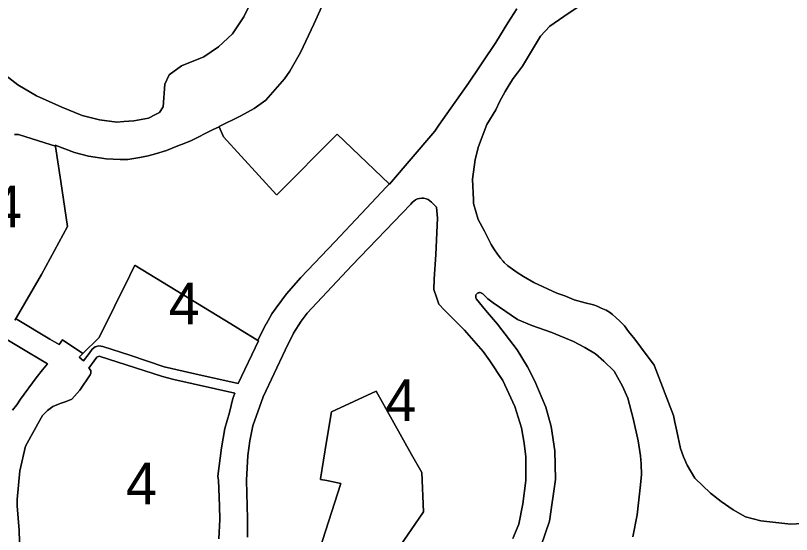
# Model space of a CAD drawing. Extents: x 598968 to 613553, y 4409678 to 4430833.
# Drawn here: x 610893 to 611116.4, y 4416459.8 to 4416609.3 of the extents above; entities that cross this region are included whole.
import ezdxf

# ---------------------------------------------------------------- set-up
doc = ezdxf.new("R2010")
doc.units = 0
doc.layers.add('1', color=7, linetype='Continuous')
doc.layers.add('ZONA 4. CASES UNIFAMILIRAS AÏLLADES EN PARCEL.LES', color=7, linetype='Continuous')

msp = doc.modelspace()

# ---------------------------------------------------------------- linework, layer by layer
at = {"layer": '1'}
for points in [[(610961.184, 4416613.8732), (610958.7248, 4416608.878), (610955.4757, 4416603.9853), (610951.4952, 4416600.27), (610947.1994, 4416597.4186), (610940.8094, 4416594.766), (610937.27, 4416592.1919), (610936.0337, 4416589.5134), (610935.5234, 4416582.9955), (610934.4335, 4416581.3607), (610933.2877, 4416580.7629), (610931.3004, 4416579.7259), (610927.04, 4416578.9784), (610924.182, 4416578.755), (610922.1426, 4416578.5957), (610917.2304, 4416579.2049), (610912.1833, 4416580.5148), (610906.335, 4416582.909), (610899.0802, 4416586.1025), (610893.7131, 4416589.3305), (610887.1816, 4416594.3181)], [(610887.1816, 4416594.3181), (610893.7131, 4416589.3305), (610899.0802, 4416586.1025), (610906.335, 4416582.909), (610912.1833, 4416580.5148), (610917.2304, 4416579.2049), (610922.1426, 4416578.5957), (610924.182, 4416578.755), (610927.04, 4416578.9784), (610931.3004, 4416579.7259), (610933.2877, 4416580.7629), (610934.4335, 4416581.3607), (610935.5234, 4416582.9955), (610936.0337, 4416589.5134), (610937.27, 4416592.1919), (610940.8094, 4416594.766), (610947.1994, 4416597.4186), (610951.4952, 4416600.27), (610955.4757, 4416603.9853), (610958.7248, 4416608.878), (610961.184, 4416613.8732)], [(610892.7107, 4416575.0409), (610893.9086, 4416575.0409), (610901.4437, 4416572.577), (610904.4817, 4416571.5979), (610904.4763, 4416571.6327), (610904.4349, 4416571.9025), (610904.4403, 4416571.9005), (610909.9969, 4416569.8168), (610914.0019, 4416568.7894), (610919.1245, 4416568.0325), (610923.1262, 4416567.8479), (610925.3954, 4416567.7714), (610928.8165, 4416568.3364), (610931.1583, 4416568.8195), (610933.3142, 4416569.4638), (610936.4387, 4416570.3976), (610939.7356, 4416571.7509), (610941.5996, 4416572.45), (610943.7244, 4416573.2468), (610949.7511, 4416576.316), (610951.6354, 4416577.2366), (610951.6236, 4416577.2639), (610951.6172, 4416577.2787), (610951.629, 4416577.2845), (610951.6172, 4416577.3118), (610957.8684, 4416580.3459), (610961.7173, 4416582.5227), (610965.0822, 4416584.9171), (610970.4878, 4416591.0592), (610972.0152, 4416593.2056), (610975.0943, 4416598.6592), (610978.9476, 4416606.7691), (610981.2076, 4416611.8791)], [(611037.339, 4416611.1665), (611034.741, 4416607.1495), (611031.2771, 4416601.5256), (611027.408, 4416595.6004), (611026.6333, 4416594.5253), (611023.4683, 4416589.764), (611014.8872, 4416577.6602), (611013.7072, 4416575.9901), (611000.7274, 4416560.7202), (611000.6511, 4416560.7926), (611000.6347, 4416560.7752), (611000.6511, 4416560.7596), (610999.8384, 4416559.8954), (610992.5548, 4416552.1508), (610984.962, 4416544.0775), (610975.1184, 4416533.8126), (610971.056, 4416529.1494), (610968.0389, 4416525.113), (610966.7828, 4416523.3187), (610965.1493, 4416520.4247), (610965.0964, 4416520.3309), (610962.7983, 4416515.6993), (610962.7932, 4416515.6891), (610962.7847, 4416515.6749), (610962.9704, 4416515.5563), (610957.1035, 4416503.2946), (610944.6427, 4416506.0886), (610935.8082, 4416508.1204), (610925.9499, 4416511.493), (610918.193, 4416513.9774), (610917.0455, 4416514.1503), (610915.9768, 4416513.8361), (610915.0964, 4416513.145), (610914.1689, 4416511.8887), (610912.6098, 4416509.8266), (610911.2976, 4416510.8447), (610912.4052, 4416511.9294), (610912.3853, 4416511.943), (610906.5731, 4416515.9097), (610905.5541, 4416514.4821), (610902.9127, 4416516.0703), (610893.4876, 4416521.7378), (610893.0763, 4416521.9612), (610892.7939, 4416521.5109)], [(611122.8662, 4416463.1736), (611116.2063, 4416462.7335), (611107.5764, 4416463.7133), (611103.2363, 4416464.8532), (611099.6665, 4416466.8631), (611096.1764, 4416469.323), (611093.1364, 4416471.673), (611088.5965, 4416476.0128), (611086.3665, 4416479.7727), (611085.3565, 4416482.1327), (611084.5165, 4416484.5926), (611083.4265, 4416489.6025), (611082.8365, 4416492.1125), (611082.4365, 4416494.1125), (611076.9266, 4416508.6123), (611072.9966, 4416513.8121), (611071.3266, 4416516.0721), (611069.5066, 4416518.302), (611068.3867, 4416519.8819), (611066.9167, 4416521.3219), (611064.9167, 4416523.1818), (611064.0267, 4416523.8118), (611063.0367, 4416524.3918), (611061.6767, 4416524.9818), (611060.4567, 4416525.5617), (611059.4168, 4416525.9117), (611057.0168, 4416526.5317), (611053.8768, 4416527.3616), (611051.1869, 4416528.5015), (611048.8869, 4416529.2614), (611042.2471, 4416532.4213), (611039.257, 4416534.1212), (611037.457, 4416535.2912), (611034.727, 4416537.1711), (611033.7371, 4416538.1811), (611033.3871, 4416538.5711), (611032.6471, 4416539.401), (611031.7371, 4416540.541), (611030.6972, 4416542.061), (611029.9871, 4416543.3609), (611028.0871, 4416547.1708), (611026.2271, 4416550.5308), (611024.8871, 4416555.1607), (611024.8271, 4416556.1607), (611024.6081, 4416562.1249), (611024.6071, 4416562.1506), (611025.3271, 4416567.7605), (611026.2671, 4416571.5305), (611028.727, 4416577.8904), (611031.347, 4416582.1404), (611032.357, 4416584.4504), (611033.977, 4416587.4004), (611035.1169, 4416589.3004), (611036.337, 4416591.1104), (611037.547, 4416592.7403), (611039.0169, 4416594.7204), (611044.2068, 4416603.3303), (611046.8467, 4416606.2304), (611050.9267, 4416608.9704), (611056.1466, 4416612.5804)], [(610959.7955, 4416459.0372), (610959.7955, 4416464.3324), (610959.7955, 4416464.3654), (610959.5093, 4416475.3822), (610959.5087, 4416475.4054), (610959.9412, 4416482.5337), (610960.519, 4416486.8192), (610961.3838, 4416491.1394), (610964.3386, 4416499.4918), (610970.6194, 4416512.8521), (610973.0698, 4416517.8203), (610975.2318, 4416521.2765), (610976.9615, 4416523.5807), (610989.8163, 4416537.2328), (611006.8247, 4416554.9458), (611007.2137, 4416555.4328), (611007.6754, 4416555.8514), (611008.1978, 4416556.1912), (611008.7678, 4416556.4434), (611009.3708, 4416556.6012), (611009.9912, 4416556.661), (611010.6132, 4416556.6211), (611011.2209, 4416556.4824), (611011.7986, 4416556.2486), (611012.3317, 4416555.9257), (611012.8065, 4416555.5219), (611014.2479, 4416554.0819), (611014.4642, 4416550.9138), (611014.4632, 4416550.8932), (611014.0325, 4416540.4424), (611013.5281, 4416533.3861), (611013.4564, 4416530.361), (611014.3208, 4416527.9139), (611014.8974, 4416526.1859), (611016.555, 4416524.3857), (611022.2594, 4416518.6572), (611027.6647, 4416512.5371), (611029.5386, 4416509.801), (611033.2861, 4416504.1128), (611036.7471, 4416496.671), (611038.6929, 4416490.5507), (611039.4857, 4416486.0865), (611039.9148, 4416482.1582), (611039.9148, 4416482.1251), (611039.9148, 4416475.3179), (611039.05, 4416468.6216), (611037.897, 4416462.7894), (611036.1672, 4416458.6131)], [(611044.3612, 4416456.5831), (611046.7583, 4416463.6503), (611048.4521, 4416475.6487), (611048.4528, 4416475.6534), (611048.2566, 4416483.8879), (611047.1955, 4416490.9158), (611045.6628, 4416496.4519), (611042.5142, 4416503.9842), (611040.4706, 4416508.0675), (611037.4054, 4416512.9751), (611031.78, 4416520.4171), (611028.3218, 4416524.4219), (611025.7674, 4416527.5627), (611025.655, 4416527.7282), (611025.5722, 4416527.9102), (611025.5218, 4416528.1038), (611025.5064, 4416528.2863), (611025.505, 4416528.3031), (611025.5224, 4416528.5022), (611025.5735, 4416528.6957), (611025.6567, 4416528.8774), (611025.7698, 4416529.0425), (611025.9092, 4416529.1858), (611026.0711, 4416529.3033), (611026.2505, 4416529.3915), (611026.4423, 4416529.448), (611026.641, 4416529.4709), (611026.8407, 4416529.4595), (611027.0355, 4416529.4144), (611027.2198, 4416529.3368), (611027.3882, 4416529.2291), (611027.5358, 4416529.0941), (611028.9721, 4416527.7089), (611030.5618, 4416526.5029), (611037.5176, 4416521.7522), (611041.644, 4416519.9855), (611047.4602, 4416517.9832), (611053.6858, 4416515.3796), (611056.9083, 4416513.6128), (611060.013, 4416511.8461), (611062.4101, 4416509.7652), (611065.3576, 4416506.8598), (611067.8004, 4416502.5221), (611069.3331, 4416499.0279), (611070.8266, 4416493.2563), (611072.2438, 4416486.7508), (611072.9512, 4416482.4319), (611073.1084, 4416480.1153), (611073.2263, 4416476.9744), (611073.2254, 4416476.9657), (611072.832, 4416473.2193), (611071.9675, 4416465.4454), (611070.7074, 4416459.0989)], [(610877.1079, 4416523.9232), (610902.1819, 4416508.9566), (610900.8029, 4416507.2609), (610898.94, 4416504.9343), (610894.477, 4416498.8147), (610893.3432, 4416497.1282), (610892.149, 4416495.6191)], [(610894.422, 4416448.185), (610894.0668, 4416460.9603), (610893.5086, 4416468.0579), (610893.4603, 4416469.924), (610894.2233, 4416478.1052), (610895.8472, 4416485.2534), (610900.3702, 4416493.3963), (610900.7761, 4416494.0553), (610902.2477, 4416495.5256), (610903.77, 4416496.641), (610905.9012, 4416497.5535), (610907.6265, 4416498.1112), (610909.2504, 4416498.8211), (610911.5336, 4416501.4066), (610914.472, 4416505.813), (610914.6625, 4416506.2569), (610914.6625, 4416506.29), (610914.6625, 4416506.6057), (610914.6625, 4416506.6388), (610914.6625, 4416506.9547), (610914.6625, 4416506.9877), (610914.135, 4416507.6695), (610916.4084, 4416510.8555), (610917.1385, 4416511.1727), (610935.3405, 4416505.2614), (610938.6179, 4416504.4396), (610956.1265, 4416500.4673), (610955.5781, 4416498.9302), (610954.6388, 4416494.9277), (610953.2687, 4416490.3143), (610952.3554, 4416484.7377), (610951.2882, 4416476.5592), (610951.2907, 4416476.5454), (610951.4912, 4416475.4439), (610951.7422, 4416468.014), (610951.8437, 4416464.1612), (610951.8432, 4416464.149), (610951.59, 4416458.5338)], [(610996.0807, 4416445.3826), (611006.9316, 4416461.1561), (611010.4947, 4416466.3358), (611009.976, 4416477.6224), (611007.0546, 4416482.8218), (610996.8137, 4416501.048), (610984.0145, 4416495.0933), (610982.5855, 4416486.5816), (610980.8698, 4416475.8276), (610980.8422, 4416475.6548), (610982.6031, 4416475.3266), (610986.6796, 4416474.4915), (610980.5379, 4416455.3781)]]:
    msp.add_lwpolyline(points, dxfattribs=at)
msp.add_lwpolyline([(611000.6347, 4416560.7752), (610985.5741, 4416575.0839), (610968.2574, 4416557.6073), (610968.1895, 4416557.6888), (610968.1179, 4416557.6165), (610952.8749, 4416574.3663), (610951.6354, 4416577.2366), (610949.7511, 4416576.316), (610943.7244, 4416573.2468), (610941.5996, 4416572.45), (610939.7356, 4416571.7509), (610936.4387, 4416570.3976), (610933.3142, 4416569.4638), (610931.1583, 4416568.8195), (610928.8165, 4416568.3364), (610925.3954, 4416567.7714), (610923.1262, 4416567.8479), (610919.1245, 4416568.0325), (610914.0019, 4416568.7894), (610909.9969, 4416569.8168), (610904.4403, 4416571.9005), (610904.4349, 4416571.9025), (610904.4763, 4416571.6327), (610904.4817, 4416571.5979), (610904.5125, 4416571.588), (610906.0394, 4416561.4712), (610907.9887, 4416548.5557), (610900.522, 4416534.665), (610893.2803, 4416522.3092), (610893.0972, 4416521.9969), (610893.0763, 4416521.9612), (610893.4876, 4416521.7378), (610902.9127, 4416516.0703), (610905.5541, 4416514.4821), (610906.5731, 4416515.9097), (610912.3853, 4416511.943), (610912.4052, 4416511.9294), (610917.0686, 4416516.4962), (610925.9387, 4416534.4256), (610927.3885, 4416537.3561), (610927.4991, 4416537.2885), (610954.9812, 4416520.4866), (610959.0741, 4416517.9844), (610961.278, 4416516.637), (610961.991, 4416516.1817), (610962.7847, 4416515.6749), (610962.7932, 4416515.6891), (610962.7983, 4416515.6993), (610965.0964, 4416520.3309), (610965.1493, 4416520.4247), (610966.7828, 4416523.3187), (610968.0389, 4416525.113), (610971.056, 4416529.1494), (610975.1184, 4416533.8126), (610984.962, 4416544.0775), (610992.5548, 4416552.1508), (610999.8384, 4416559.8954), (611000.6511, 4416560.7596)], close=True, dxfattribs=at)
at = {"layer": 'ZONA 4. CASES UNIFAMILIRAS AÏLLADES EN PARCEL.LES'}
for points in [[(610981.2076, 4416611.8791), (610978.9476, 4416606.7691), (610975.0943, 4416598.6592), (610972.0152, 4416593.2056), (610970.4878, 4416591.0592), (610965.0822, 4416584.9171), (610961.7173, 4416582.5227), (610957.8684, 4416580.3459), (610951.6172, 4416577.3118), (610951.629, 4416577.2845), (610951.6172, 4416577.2787), (610951.6236, 4416577.2639), (610951.6354, 4416577.2366), (610952.8749, 4416574.3663), (610968.1179, 4416557.6165), (610968.1895, 4416557.6888), (610968.2574, 4416557.6073), (610985.5741, 4416575.0839), (611000.6347, 4416560.7752), (611000.6511, 4416560.7926), (611000.7274, 4416560.7202), (611013.7072, 4416575.9901), (611014.8872, 4416577.6602), (611023.4683, 4416589.764), (611026.6333, 4416594.5253), (611027.408, 4416595.6004), (611031.2771, 4416601.5256), (611034.741, 4416607.1495), (611037.339, 4416611.1665)], [(611056.1466, 4416612.5804), (611050.9267, 4416608.9704), (611046.8467, 4416606.2304), (611044.2068, 4416603.3303), (611039.0169, 4416594.7204), (611037.547, 4416592.7403), (611036.337, 4416591.1104), (611035.1169, 4416589.3004), (611033.977, 4416587.4004), (611032.357, 4416584.4504), (611031.347, 4416582.1404), (611028.727, 4416577.8904), (611026.2671, 4416571.5305), (611025.3271, 4416567.7605), (611024.6071, 4416562.1506), (611024.6081, 4416562.1249), (611024.8271, 4416556.1607), (611024.8871, 4416555.1607), (611026.2271, 4416550.5308), (611028.0871, 4416547.1708), (611029.9871, 4416543.3609), (611030.6972, 4416542.061), (611031.7371, 4416540.541), (611032.6471, 4416539.401), (611033.3871, 4416538.5711), (611033.7371, 4416538.1811), (611034.727, 4416537.1711), (611037.457, 4416535.2912), (611039.257, 4416534.1212), (611042.2471, 4416532.4213), (611048.8869, 4416529.2614), (611051.1869, 4416528.5015), (611053.8768, 4416527.3616), (611057.0168, 4416526.5317), (611059.4168, 4416525.9117), (611060.4567, 4416525.5617), (611061.6767, 4416524.9818), (611063.0367, 4416524.3918), (611064.0267, 4416523.8118), (611064.9167, 4416523.1818), (611066.9167, 4416521.3219), (611068.3867, 4416519.8819), (611069.5066, 4416518.302), (611071.3266, 4416516.0721), (611072.9966, 4416513.8121), (611076.9266, 4416508.6123), (611082.4365, 4416494.1125), (611082.8365, 4416492.1125), (611083.4265, 4416489.6025), (611084.5165, 4416484.5926), (611085.3565, 4416482.1327), (611086.3665, 4416479.7727), (611088.5965, 4416476.0128), (611093.1364, 4416471.673), (611096.1764, 4416469.323), (611099.6665, 4416466.8631), (611103.2363, 4416464.8532), (611107.5764, 4416463.7133), (611116.2063, 4416462.7335), (611122.8662, 4416463.1736)], [(610892.7939, 4416521.5109), (610893.0763, 4416521.9612), (610893.0972, 4416521.9969), (610893.2803, 4416522.3092), (610900.522, 4416534.665), (610907.9887, 4416548.5557), (610906.0394, 4416561.4712), (610904.5125, 4416571.588), (610904.4817, 4416571.5979), (610901.4437, 4416572.577), (610893.9086, 4416575.0409), (610892.7107, 4416575.0409)], [(611036.1672, 4416458.6131), (611037.897, 4416462.7894), (611039.05, 4416468.6216), (611039.9148, 4416475.3179), (611039.9148, 4416482.1251), (611039.9148, 4416482.1582), (611039.4857, 4416486.0865), (611038.6929, 4416490.5507), (611036.7471, 4416496.671), (611033.2861, 4416504.1128), (611029.5386, 4416509.801), (611027.6647, 4416512.5371), (611022.2594, 4416518.6572), (611016.555, 4416524.3857), (611014.8974, 4416526.1859), (611014.3208, 4416527.9139), (611013.4564, 4416530.361), (611013.5281, 4416533.3861), (611014.0325, 4416540.4424), (611014.4632, 4416550.8932), (611014.4642, 4416550.9138), (611014.2479, 4416554.0819), (611012.8065, 4416555.5219), (611012.3317, 4416555.9257), (611011.7986, 4416556.2486), (611011.2209, 4416556.4824), (611010.6132, 4416556.6211), (611009.9912, 4416556.661), (611009.3708, 4416556.6012), (611008.7678, 4416556.4434), (611008.1978, 4416556.1912), (611007.6754, 4416555.8514), (611007.2137, 4416555.4328), (611006.8247, 4416554.9458), (610989.8163, 4416537.2328), (610976.9615, 4416523.5807), (610975.2318, 4416521.2765), (610973.0698, 4416517.8203), (610970.6194, 4416512.8521), (610964.3386, 4416499.4918), (610961.3838, 4416491.1394), (610960.519, 4416486.8192), (610959.9412, 4416482.5337), (610959.5087, 4416475.4054), (610959.5093, 4416475.3822), (610959.7955, 4416464.3654), (610959.7955, 4416464.3324), (610959.7955, 4416459.0372)], [(611070.7074, 4416459.0989), (611071.9675, 4416465.4454), (611072.832, 4416473.2193), (611073.2254, 4416476.9657), (611073.2263, 4416476.9744), (611073.1084, 4416480.1153), (611072.9512, 4416482.4319), (611072.2438, 4416486.7508), (611070.8266, 4416493.2563), (611069.3331, 4416499.0279), (611067.8004, 4416502.5221), (611065.3576, 4416506.8598), (611062.4101, 4416509.7652), (611060.013, 4416511.8461), (611056.9083, 4416513.6128), (611053.6858, 4416515.3796), (611047.4602, 4416517.9832), (611041.644, 4416519.9855), (611037.5176, 4416521.7522), (611030.5618, 4416526.5029), (611028.9721, 4416527.7089), (611027.5358, 4416529.0941), (611027.3882, 4416529.2291), (611027.2198, 4416529.3368), (611027.0355, 4416529.4144), (611026.8407, 4416529.4595), (611026.641, 4416529.4709), (611026.4423, 4416529.448), (611026.2505, 4416529.3915), (611026.0711, 4416529.3033), (611025.9092, 4416529.1858), (611025.7698, 4416529.0425), (611025.6567, 4416528.8774), (611025.5735, 4416528.6957), (611025.5224, 4416528.5022), (611025.505, 4416528.3031), (611025.5064, 4416528.2863), (611025.5218, 4416528.1038), (611025.5722, 4416527.9102), (611025.655, 4416527.7282), (611025.7674, 4416527.5627), (611028.3218, 4416524.4219), (611031.78, 4416520.4171), (611037.4054, 4416512.9751), (611040.4706, 4416508.0675), (611042.5142, 4416503.9842), (611045.6628, 4416496.4519), (611047.1955, 4416490.9158), (611048.2566, 4416483.8879), (611048.4528, 4416475.6534), (611048.4521, 4416475.6487), (611046.7583, 4416463.6503), (611044.3612, 4416456.5831)], [(610892.149, 4416495.6191), (610893.3432, 4416497.1282), (610894.477, 4416498.8147), (610898.94, 4416504.9343), (610900.8029, 4416507.2609), (610902.1819, 4416508.9566), (610877.1079, 4416523.9232)], [(610951.59, 4416458.5338), (610951.8432, 4416464.149), (610951.8437, 4416464.1612), (610951.7422, 4416468.014), (610951.4912, 4416475.4439), (610951.2907, 4416476.5454), (610951.2882, 4416476.5592), (610952.3554, 4416484.7377), (610953.2687, 4416490.3143), (610954.6388, 4416494.9277), (610955.5781, 4416498.9302), (610956.1265, 4416500.4673), (610938.6179, 4416504.4396), (610935.3405, 4416505.2614), (610917.1385, 4416511.1727), (610916.4084, 4416510.8555), (610914.135, 4416507.6695), (610914.6625, 4416506.9877), (610914.6625, 4416506.9547), (610914.6625, 4416506.6388), (610914.6625, 4416506.6057), (610914.6625, 4416506.29), (610914.6625, 4416506.2569), (610914.472, 4416505.813), (610911.5336, 4416501.4066), (610909.2504, 4416498.8211), (610907.6265, 4416498.1112), (610905.9012, 4416497.5535), (610903.77, 4416496.641), (610902.2477, 4416495.5256), (610900.7761, 4416494.0553), (610900.3702, 4416493.3963), (610895.8472, 4416485.2534), (610894.2233, 4416478.1052), (610893.4603, 4416469.924), (610893.5086, 4416468.0579), (610894.0668, 4416460.9603), (610894.422, 4416448.185)], [(610980.5379, 4416455.3781), (610986.6796, 4416474.4915), (610982.6031, 4416475.3266), (610980.8422, 4416475.6548), (610980.8698, 4416475.8276), (610982.5855, 4416486.5816), (610984.0145, 4416495.0933), (610996.8137, 4416501.048), (611007.0546, 4416482.8218), (611009.976, 4416477.6224), (611010.4947, 4416466.3358), (611006.9316, 4416461.1561), (610996.0807, 4416445.3826)]]:
    msp.add_lwpolyline(points, dxfattribs=at)
msp.add_lwpolyline([(610962.7847, 4416515.6749), (610961.991, 4416516.1817), (610961.278, 4416516.637), (610959.0741, 4416517.9844), (610954.9812, 4416520.4866), (610927.4991, 4416537.2885), (610927.3885, 4416537.3561), (610925.9387, 4416534.4256), (610917.0686, 4416516.4962), (610912.4052, 4416511.9294), (610911.2976, 4416510.8447), (610912.6098, 4416509.8266), (610914.1689, 4416511.8887), (610915.0964, 4416513.145), (610915.9768, 4416513.8361), (610917.0455, 4416514.1503), (610918.193, 4416513.9774), (610925.9499, 4416511.493), (610935.8082, 4416508.1204), (610944.6427, 4416506.0886), (610957.1035, 4416503.2946), (610962.9704, 4416515.5563)], close=True, dxfattribs=at)

# ---------------------------------------------------------------- texts
for p in [(610885.9803, 4416548.265), (610937.134, 4416520.3254), (610999.4965, 4416492.4898), (610924.7934, 4416468.5009)]:
    msp.add_text('4', height=12, dxfattribs=at).set_placement(p)

doc.saveas('drawing.dxf')
